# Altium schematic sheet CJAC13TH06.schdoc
size 127 x 101 mm
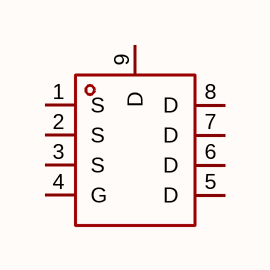
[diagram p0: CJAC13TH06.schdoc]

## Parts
Q?  cjac13th06  [PDFN-8_L5.8-W4.9-P1.27-LS6.1-BL]  (value not drawn)

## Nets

Not connected (* = marked no-connect by the designer): Q? 1(S) 2(S) 3(S) 4(G) 5(D) 6(D) 7(D) 8(D) 9(D)

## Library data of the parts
Q? = cjac13th06: 数量:1个N沟道;漏源电压(Vdss):60V;连续漏极电流(Id):130A;导通电阻(RDS(on)):2.2mΩ@10V;耗散功率(Pd):140W;阈值电压(Vgs(th)):1V;; Manufacturer: CJ(江苏长电/长晶); AddInBom: yes; ModelId: e4f86a8f30fa4f6d9bf0edb4447c4e78; ModelTransform: 196.85,238.189,0,0,0,0,-0.005,-3.265,0; Number: 1个N沟道; Drain to Source Voltage: 60V; Current - Continuous Drain(Id): 130A; Pd - Power Dissipation: 140W; Gate Threshold Voltage (Vgs(th)): 1V; Gate Charge(Qg): 63.7nC@10V; Input Capacitance(Ciss): 5.298nF; Reverse Transfer Capacitance (Crss@Vds): 74.8pF; Type: N沟道; Output Capacitance(Coss): 1.635nF; Vgs: ±20V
